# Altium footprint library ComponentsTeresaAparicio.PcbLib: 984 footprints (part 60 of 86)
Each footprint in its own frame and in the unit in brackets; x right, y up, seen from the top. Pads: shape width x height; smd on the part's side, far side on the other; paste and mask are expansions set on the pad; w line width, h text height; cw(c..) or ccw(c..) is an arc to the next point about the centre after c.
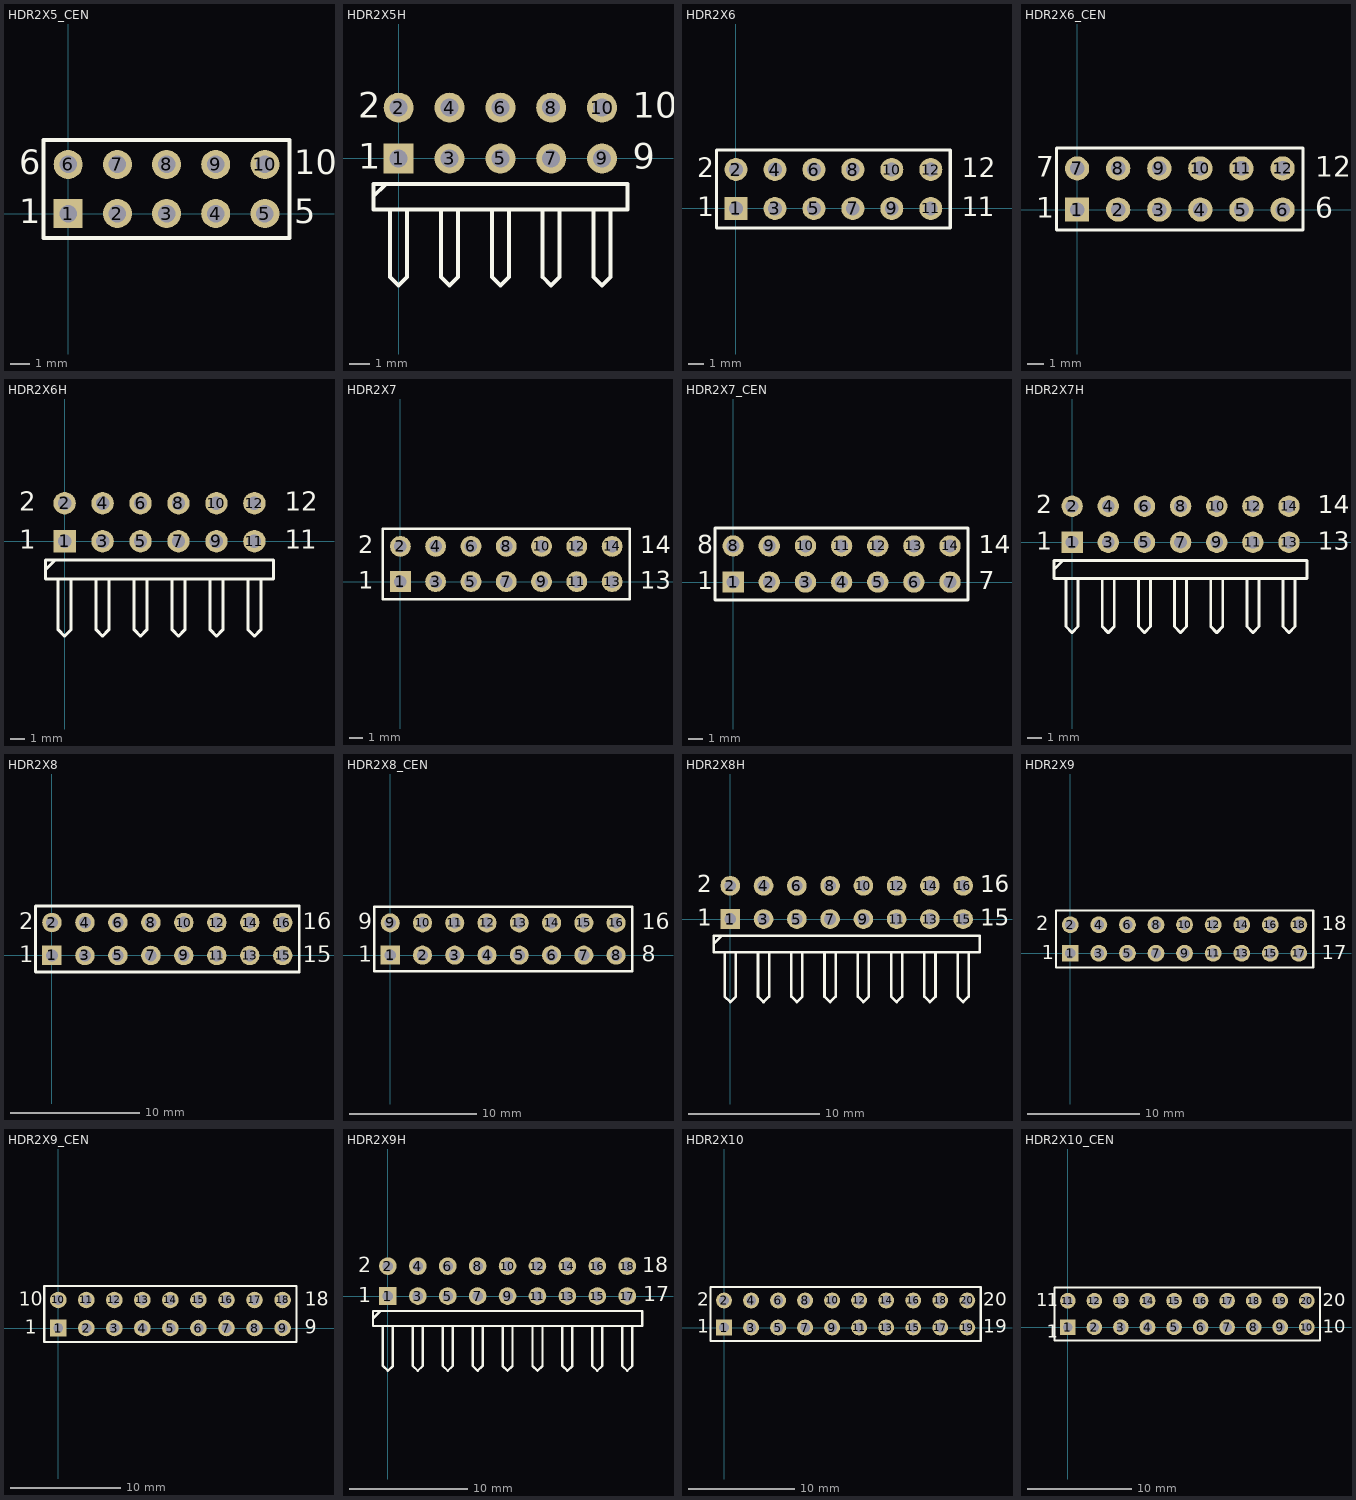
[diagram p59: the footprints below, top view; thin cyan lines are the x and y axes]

## HDR2X5_CEN [mm] "Connector; Header; 5x2 Position"
pads (10):
  rect 1.5x1.5 hole 0.9: 1(0,0)
  round 1.5 hole 0.9: 2(2.54,0) 3(5.08,0) 4(7.62,0) 5(10.16,0) 6(0,2.54) 7(2.54,2.54) 8(5.08,2.54) 9(7.62,2.54) 10(10.16,2.54)
Top Overlay:
  lines w0.2: -1.27,-1.27 11.43,-1.27 11.43,3.81 -1.27,3.81 -1.27,-1.27
  text "1" at -2.54,-0.508 h1.27
  text "5" at 11.684,-0.508 h1.27
  text "10" at 11.684,2.032 h1.27
  text "6" at -2.54,2.032 h1.27

## HDR2X5H [mm] "Connector; Header; 5x2 Position; Right Angle"
pads (10):
  rect 1.5x1.5 hole 0.9: 1(0,0)
  round 1.5 hole 0.9: 2(0,2.54) 3(2.54,0) 4(2.54,2.54) 5(5.08,0) 6(5.08,2.54) 7(7.62,0) 8(7.62,2.54) 9(10.16,0) 10(10.16,2.54)
Top Overlay:
  lines w0.2: -1.27,-1.905 -0.635,-1.27 ; -0.423,-2.54 -0.423,-5.927 0,-6.35 0.423,-5.927 0.423,-2.54 ; 2.117,-2.54 2.117,-5.927 2.54,-6.35 2.963,-5.927 2.963,-2.54 ; 4.657,-2.54 4.657,-5.927 5.08,-6.35 5.503,-5.927 5.503,-2.54 ; 7.197,-2.54 7.197,-5.927 7.62,-6.35 8.043,-5.927 8.043,-2.54 ; 9.737,-2.54 9.737,-5.927 10.16,-6.35 10.583,-5.927 10.583,-2.54 ; -1.27,-2.54 11.43,-2.54 11.43,-1.27 -1.27,-1.27 -1.27,-2.54
  text "2" at -2.032,2.032 h1.27
  text "1" at -2.032,-0.508 h1.27
  text "9" at 11.684,-0.508 h1.27
  text "10" at 11.684,2.032 h1.27

## HDR2X6 [mm] "Connector; Header; 6x2 Position"
pads (12):
  rect 1.5x1.5 hole 0.9: 1(0,0)
  round 1.5 hole 0.9: 2(0,2.54) 3(2.54,0) 4(2.54,2.54) 5(5.08,0) 6(5.08,2.54) 7(7.62,0) 8(7.62,2.54) 9(10.16,0) 10(10.16,2.54) 11(12.7,0) 12(12.7,2.54)
Top Overlay:
  lines w0.2: -1.27,-1.27 -1.27,3.81 13.97,3.81 13.97,-1.27 -1.27,-1.27
  text "2" at -2.54,2.032 h1.27
  text "1" at -2.54,-0.508 h1.27
  text "1" at 14.732,-0.508 h1.27
  text "1" at 15.748,-0.508 h1.27
  text "12" at 14.732,2.032 h1.27

## HDR2X6_CEN [mm] "Connector; Header; 6x2 Position"
pads (12):
  rect 1.5x1.5 hole 0.9: 1(0,0)
  round 1.5 hole 0.9: 2(2.54,0) 3(5.08,0) 4(7.62,0) 5(10.16,0) 6(12.7,0) 7(0,2.54) 8(2.54,2.54) 9(5.08,2.54) 10(7.62,2.54) 11(10.16,2.54) 12(12.7,2.54)
Top Overlay:
  lines w0.2: -1.27,-1.27 13.97,-1.27 13.97,3.81 -1.27,3.81 -1.27,-1.27
  text "12" at 14.732,2.032 h1.27
  text "6" at 14.732,-0.508 h1.27
  text "1" at -2.54,-0.508 h1.27
  text "7" at -2.54,2.032 h1.27

## HDR2X6H [mm] "Connector; Header; 6x2 Position; Right Angle"
pads (12):
  rect 1.5x1.5 hole 0.9: 1(0,0)
  round 1.5 hole 0.9: 2(0,2.54) 3(2.54,0) 4(2.54,2.54) 5(5.08,0) 6(5.08,2.54) 7(7.62,0) 8(7.62,2.54) 9(10.16,0) 10(10.16,2.54) 11(12.7,0) 12(12.7,2.54)
Top Overlay:
  lines w0.2: -1.27,-1.905 -0.635,-1.27 ; -0.423,-2.54 -0.423,-5.927 0,-6.35 0.423,-5.927 0.423,-2.54 ; 2.117,-2.54 2.117,-5.927 2.54,-6.35 2.963,-5.927 2.963,-2.54 ; 4.657,-2.54 4.657,-5.927 5.08,-6.35 5.503,-5.927 5.503,-2.54 ; 7.197,-2.54 7.197,-5.927 7.62,-6.35 8.043,-5.927 8.043,-2.54 ; 9.737,-2.54 9.737,-5.927 10.16,-6.35 10.583,-5.927 10.583,-2.54 ; 12.277,-2.54 12.277,-5.927 12.7,-6.35 13.123,-5.927 13.123,-2.54 ; -1.27,-2.54 13.97,-2.54 13.97,-1.27 -1.27,-1.27 -1.27,-2.54
  text "2" at -3.048,2.032 h1.27
  text "1" at -3.048,-0.508 h1.27
  text "1" at 14.732,-0.508 h1.27
  text "1" at 15.748,-0.508 h1.27
  text "12" at 14.732,2.032 h1.27

## HDR2X7 [mm] "Connector; Header; 7x2 Position"
pads (14):
  rect 1.5x1.5 hole 0.9: 1(0,0)
  round 1.5 hole 0.9: 2(0,2.54) 3(2.54,0) 4(2.54,2.54) 5(5.08,0) 6(5.08,2.54) 7(7.62,0) 8(7.62,2.54) 9(10.16,0) 10(10.16,2.54) 11(12.7,0) 12(12.7,2.54) 13(15.24,0) 14(15.24,2.54)
Top Overlay:
  lines w0.2: -1.27,-1.27 16.51,-1.27 16.51,3.81 -1.27,3.81 -1.27,-1.27
  text "13" at 17.272,-0.508 h1.27
  text "14" at 17.272,2.032 h1.27
  text "1" at -3.048,-0.508 h1.27
  text "2" at -3.048,2.032 h1.27

## HDR2X7_CEN [mm] "Connector; Header; 7x2 Position"
pads (14):
  rect 1.5x1.5 hole 0.9: 1(0,0)
  round 1.5 hole 0.9: 2(2.54,0) 3(5.08,0) 4(7.62,0) 5(10.16,0) 6(12.7,0) 7(15.24,0) 8(0,2.54) 9(2.54,2.54) 10(5.08,2.54) 11(7.62,2.54) 12(10.16,2.54) 13(12.7,2.54) 14(15.24,2.54)
Top Overlay:
  lines w0.2: -1.27,-1.27 16.51,-1.27 16.51,3.81 -1.27,3.81 -1.27,-1.27
  text "8" at -2.54,2.032 h1.27
  text "1" at -2.54,-0.508 h1.27
  text "7" at 17.272,-0.508 h1.27
  text "14" at 17.272,2.032 h1.27

## HDR2X7H [mm] "Connector; Header; 7x2 Position; Right Angle"
pads (14):
  rect 1.5x1.5 hole 0.9: 1(0,0)
  round 1.5 hole 0.9: 2(0,2.54) 3(2.54,0) 4(2.54,2.54) 5(5.08,0) 6(5.08,2.54) 7(7.62,0) 8(7.62,2.54) 9(10.16,0) 10(10.16,2.54) 11(12.7,0) 12(12.7,2.54) 13(15.24,0) 14(15.24,2.54)
Top Overlay:
  lines w0.2: -1.27,-1.905 -0.635,-1.27 ; -0.423,-2.54 -0.423,-5.927 0,-6.35 0.423,-5.927 0.423,-2.54 ; 2.117,-2.54 2.117,-5.927 2.54,-6.35 2.963,-5.927 2.963,-2.54 ; 4.657,-2.54 4.657,-5.927 5.08,-6.35 5.503,-5.927 5.503,-2.54 ; 7.197,-2.54 7.197,-5.927 7.62,-6.35 8.043,-5.927 8.043,-2.54 ; 9.737,-2.54 9.737,-5.927 10.16,-6.35 10.583,-5.927 10.583,-2.54 ; 12.277,-2.54 12.277,-5.927 12.7,-6.35 13.123,-5.927 13.123,-2.54 ; 14.817,-2.54 14.817,-5.927 15.24,-6.35 15.663,-5.927 15.663,-2.54 ; -1.27,-2.54 -1.27,-1.27 16.51,-1.27 16.51,-2.54 -1.27,-2.54
  text "2" at -2.54,2.032 h1.27
  text "1" at -2.54,-0.508 h1.27
  text "13" at 17.272,-0.508 h1.27
  text "14" at 17.272,2.032 h1.27

## HDR2X8 [mm] "Connector; Header; 8x2 Position"
pads (16):
  rect 1.5x1.5 hole 0.9: 1(0,0)
  round 1.5 hole 0.9: 2(0,2.54) 3(2.54,0) 4(2.54,2.54) 5(5.08,0) 6(5.08,2.54) 7(7.62,0) 8(7.62,2.54) 9(10.16,0) 10(10.16,2.54) 11(12.7,0) 12(12.7,2.54) 13(15.24,0) 14(15.24,2.54) 15(17.78,0) 16(17.78,2.54)
Top Overlay:
  lines w0.2: -1.27,-1.27 19.05,-1.27 19.05,3.81 -1.27,3.81 -1.27,-1.27
  text "16" at 19.304,2.032 h1.27
  text "15" at 19.304,-0.508 h1.27
  text "1" at -2.54,-0.508 h1.27
  text "2" at -2.54,2.032 h1.27

## HDR2X8_CEN [mm] "Connector; Header; 8x2 Position"
pads (16):
  rect 1.5x1.5 hole 0.9: 1(0,0)
  round 1.5 hole 0.9: 2(2.54,0) 3(5.08,0) 4(7.62,0) 5(10.16,0) 6(12.7,0) 7(15.24,0) 8(17.78,0) 9(0,2.54) 10(2.54,2.54) 11(5.08,2.54) 12(7.62,2.54) 13(10.16,2.54) 14(12.7,2.54) 15(15.24,2.54) 16(17.78,2.54)
Top Overlay:
  lines w0.2: -1.27,-1.27 -1.27,3.81 19.05,3.81 19.05,-1.27 -1.27,-1.27
  text "9" at -2.54,2.032 h1.27
  text "1" at -2.54,-0.508 h1.27
  text "8" at 19.812,-0.508 h1.27
  text "16" at 19.812,2.032 h1.27

## HDR2X8H [mm] "Connector; Header; 8x2 Position; Right Angle"
pads (16):
  rect 1.5x1.5 hole 0.9: 1(0,0)
  round 1.5 hole 0.9: 2(0,2.54) 3(2.54,0) 4(2.54,2.54) 5(5.08,0) 6(5.08,2.54) 7(7.62,0) 8(7.62,2.54) 9(10.16,0) 10(10.16,2.54) 11(12.7,0) 12(12.7,2.54) 13(15.24,0) 14(15.24,2.54) 15(17.78,0) 16(17.78,2.54)
Top Overlay:
  lines w0.2: -1.27,-1.905 -0.635,-1.27 ; -0.423,-2.54 -0.423,-5.927 0,-6.35 0.423,-5.927 0.423,-2.54 ; 2.117,-2.54 2.117,-5.927 2.54,-6.35 2.963,-5.927 2.963,-2.54 ; 4.657,-2.54 4.657,-5.927 5.08,-6.35 5.503,-5.927 5.503,-2.54 ; 7.197,-2.54 7.197,-5.927 7.62,-6.35 8.043,-5.927 8.043,-2.54 ; 9.737,-2.54 9.737,-5.927 10.16,-6.35 10.583,-5.927 10.583,-2.54 ; 12.277,-2.54 12.277,-5.927 12.7,-6.35 13.123,-5.927 13.123,-2.54 ; 14.817,-2.54 14.817,-5.927 15.24,-6.35 15.663,-5.927 15.663,-2.54 ; 17.357,-2.54 17.357,-5.927 17.78,-6.35 18.203,-5.927 18.203,-2.54 ; -1.27,-2.54 19.05,-2.54 19.05,-1.27 -1.27,-1.27 -1.27,-2.54
  text "16" at 19.092,2.032 h1.27
  text "15" at 19.069,-0.508 h1.27
  text "1" at -2.54,-0.508 h1.27
  text "2" at -2.54,2.032 h1.27

## HDR2X9 [mm] "Connector; Header; 9x2 Position"
pads (18):
  rect 1.5x1.5 hole 0.9: 1(0,0)
  round 1.5 hole 0.9: 2(0,2.54) 3(2.54,0) 4(2.54,2.54) 5(5.08,0) 6(5.08,2.54) 7(7.62,0) 8(7.62,2.54) 9(10.16,0) 10(10.16,2.54) 11(12.7,0) 12(12.7,2.54) 13(15.24,0) 14(15.24,2.54) 15(17.78,0) 16(17.78,2.54) 17(20.32,0) 18(20.32,2.54)
Top Overlay:
  lines w0.2: -1.27,-1.27 -1.27,3.81 21.59,3.81 21.59,-1.27 -1.27,-1.27
  text "2" at -3.048,2.032 h1.27
  text "1" at -2.54,-0.508 h1.27
  text "17" at 22.352,-0.508 h1.27
  text "18" at 22.352,2.032 h1.27

## HDR2X9_CEN [mm] "Connector; Header; 9x2 Position"
pads (18):
  rect 1.5x1.5 hole 0.9: 1(0,0)
  round 1.5 hole 0.9: 2(2.54,0) 3(5.08,0) 4(7.62,0) 5(10.16,0) 6(12.7,0) 7(15.24,0) 8(17.78,0) 9(20.32,0) 10(0,2.54) 11(2.54,2.54) 12(5.08,2.54) 13(7.62,2.54) 14(10.16,2.54) 15(12.7,2.54) 16(15.24,2.54) 17(17.78,2.54) 18(20.32,2.54)
Top Overlay:
  lines w0.2: -1.27,-1.27 21.59,-1.27 21.59,3.81 -1.27,3.81 -1.27,-1.27
  text "18" at 22.352,2.032 h1.27
  text "9" at 22.352,-0.508 h1.27
  text "1" at -3.048,-0.508 h1.27
  text "10" at -3.556,2.032 h1.27

## HDR2X9H [mm] "Connector; Header; 9x2 Position; Right Angle"
pads (18):
  rect 1.5x1.5 hole 0.9: 1(0,0)
  round 1.5 hole 0.9: 2(0,2.54) 3(2.54,0) 4(2.54,2.54) 5(5.08,0) 6(5.08,2.54) 7(7.62,0) 8(7.62,2.54) 9(10.16,0) 10(10.16,2.54) 11(12.7,0) 12(12.7,2.54) 13(15.24,0) 14(15.24,2.54) 15(17.78,0) 16(17.78,2.54) 17(20.32,0) 18(20.32,2.54)
Top Overlay:
  lines w0.2: -1.27,-1.905 -0.635,-1.27 ; -0.423,-2.54 -0.423,-5.927 0,-6.35 0.423,-5.927 0.423,-2.54 ; 2.117,-2.54 2.117,-5.927 2.54,-6.35 2.963,-5.927 2.963,-2.54 ; 4.657,-2.54 4.657,-5.927 5.08,-6.35 5.503,-5.927 5.503,-2.54 ; 7.197,-2.54 7.197,-5.927 7.62,-6.35 8.043,-5.927 8.043,-2.54 ; 9.737,-2.54 9.737,-5.927 10.16,-6.35 10.583,-5.927 10.583,-2.54 ; 12.277,-2.54 12.277,-5.927 12.7,-6.35 13.123,-5.927 13.123,-2.54 ; 14.817,-2.54 14.817,-5.927 15.24,-6.35 15.663,-5.927 15.663,-2.54 ; 17.357,-2.54 17.357,-5.927 17.78,-6.35 18.203,-5.927 18.203,-2.54 ; 19.897,-2.54 19.897,-5.927 20.32,-6.35 20.743,-5.927 20.743,-2.54 ; -1.27,-2.54 21.59,-2.54 21.59,-1.27 -1.27,-1.27 -1.27,-2.54
  text "2" at -2.54,2.032 h1.27
  text "18" at 21.593,2.032 h1.27
  text "17" at 21.664,-0.44 h1.27
  text "1" at -2.54,-0.508 h1.27

## HDR2X10 [mm] "Connector; Header; 10x2 Position"
pads (20):
  rect 1.5x1.5 hole 0.9: 1(0,0)
  round 1.5 hole 0.9: 2(0,2.54) 3(2.54,0) 4(2.54,2.54) 5(5.08,0) 6(5.08,2.54) 7(7.62,0) 8(7.62,2.54) 9(10.16,0) 10(10.16,2.54) 11(12.7,0) 12(12.7,2.54) 13(15.24,0) 14(15.24,2.54) 15(17.78,0) 16(17.78,2.54) 17(20.32,0) 18(20.32,2.54) 19(22.86,0) 20(22.86,2.54)
Top Overlay:
  lines w0.2: -1.27,-1.27 -1.27,3.81 0.635,3.81 24.13,3.81 24.13,-1.27 0.635,-1.27 -1.27,-1.27
  text "2" at -2.54,2.032 h1.27
  text "1" at -2.54,-0.508 h1.27
  text "19" at 24.384,-0.508 h1.27
  text "20" at 24.384,2.032 h1.27

## HDR2X10_CEN [mm] "Connector; Header; 10x2 Position"
pads (20):
  rect 1.5x1.5 hole 0.9: 1(0,0)
  round 1.5 hole 0.9: 2(2.54,0) 3(5.08,0) 4(7.62,0) 5(10.16,0) 6(12.7,0) 7(15.24,0) 8(17.78,0) 9(20.32,0) 10(22.86,0) 11(0,2.54) 12(2.54,2.54) 13(5.08,2.54) 14(7.62,2.54) 15(10.16,2.54) 16(12.7,2.54) 17(15.24,2.54) 18(17.78,2.54) 19(20.32,2.54) 20(22.86,2.54)
Top Overlay:
  lines w0.2: -1.27,-1.27 24.13,-1.27 24.13,3.81 -1.27,3.81 -1.27,-1.27
  text "1" at -2.032,-1.016 h1.27
  text "1" at -3.048,2.032 h1.27
  text "1" at -2.032,2.032 h1.27
  text "10" at 24.384,-0.508 h1.27
  text "20" at 24.384,2.032 h1.27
